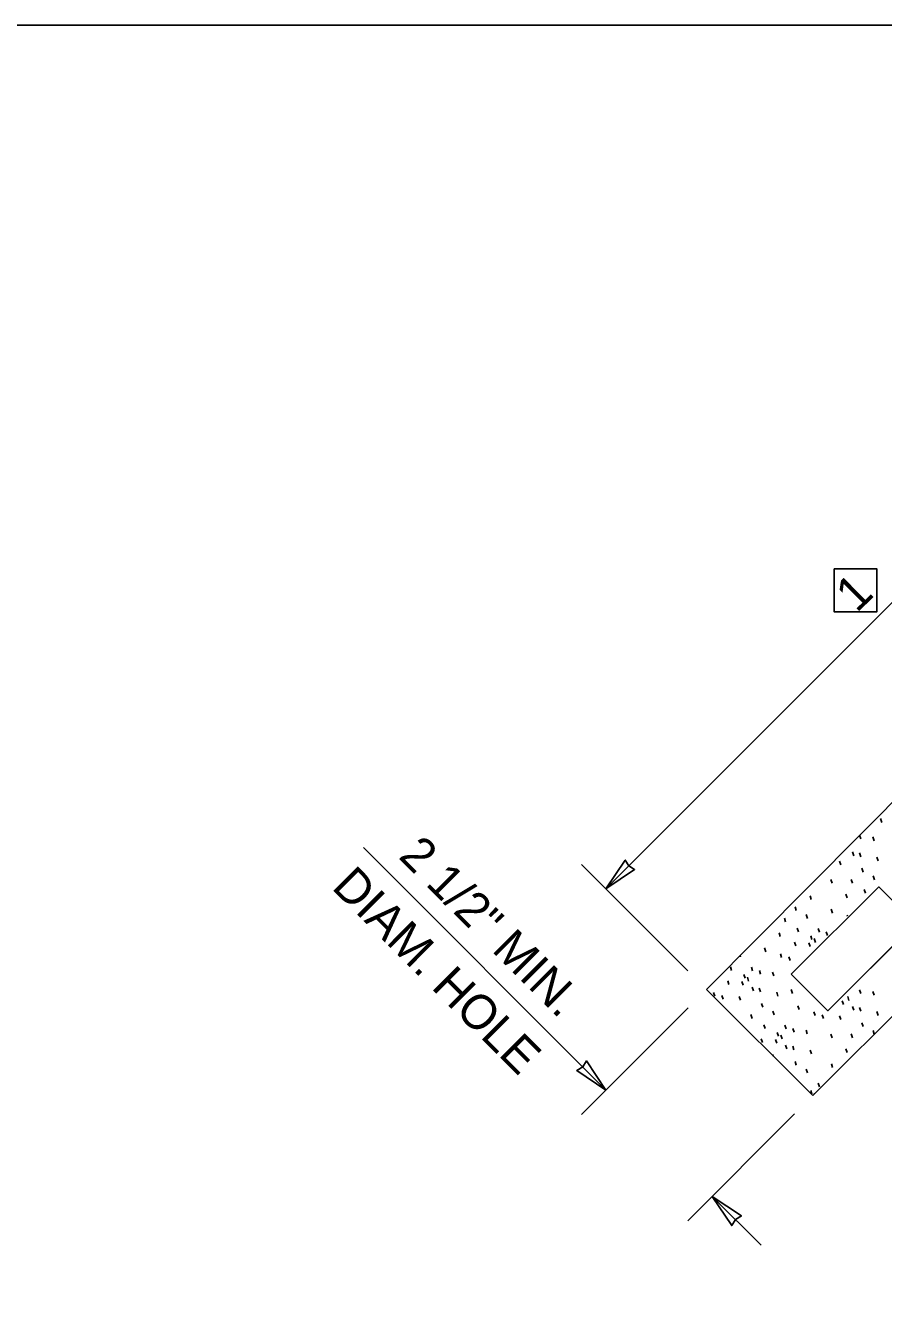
# Model space of a CAD drawing. Extents: x 99861 to 103151, y 100000 to 102076.
# Drawn here: x 101342 to 101740, y 101489 to 102076 of the extents above; entities that cross this region are included whole.
import ezdxf

# ---------------------------------------------------------------- set-up
doc = ezdxf.new("R2010")
doc.units = 0
for name, color, linetype in [('Level 1', 7, 'Continuous'), ('Level 15', 7, 'Continuous'), ('Level 2', 7, 'Continuous'), ('Level 20', 7, 'Continuous'), ('Level 6', 7, 'Continuous'), ('Level 8', 7, 'Continuous')]:
    doc.layers.add(name, color=color, linetype=linetype)

# ---------------------------------------------------------------- blocks, each defined once
blk = doc.blocks.new('T')
at = {"layer": 'Level 15'}
blk.add_lwpolyline([(0, 0), (-22.829, 2.985), (-21.773, 0), (-22.83, -2.985)], close=True, dxfattribs=at)

msp = doc.modelspace()

# ---------------------------------------------------------------- linework, layer by layer
at = {"layer": 'Level 1'}
msp.add_lwpolyline([(99861, 100000), (103150, 100000), (103150, 102076), (99861, 102076)], close=True, dxfattribs=at)
at = {"layer": 'Level 15'}
for p, q in [((101953.07, 102017.81), (101611.31, 101675.88)), ((101599.99, 101687.19), (101649.29, 101637.91))]:
    msp.add_line(p, q, dxfattribs=at)
msp.add_lwpolyline([(101611.31, 101675.88), (101620.24, 101689.18), (101621.91, 101686.49), (101624.6, 101684.82)], close=True, dxfattribs=at)
at = {"layer": 'Level 2'}
for p, q in [((101805.19, 101777.43), (101657.99, 101629.22)), ((101854.86, 101727.74), (101707.23, 101580.01)), ((101707.23, 101580.01), (101657.99, 101629.22))]:
    msp.add_line(p, q, dxfattribs=at)
at = {"layer": 'Level 20'}
for p, q in [((101498.85, 101694.95), (101611.33, 101582.54)), ((101649.5, 101620.73), (101600.02, 101571.22)), ((101698.75, 101571.52), (101649.27, 101522.01)), ((101660.58, 101533.33), (101683.21, 101510.71)), ((101671.89, 101522.02), (101660.58, 101533.33))]:
    msp.add_line(p, q, dxfattribs=at)
msp.add_lwpolyline([(101717.08, 101824.1), (101736.94, 101824.1), (101736.94, 101804.25), (101717.08, 101804.25)], close=True, dxfattribs=at)
at = {"layer": 'Level 6'}
for p, q in [((101697.21, 101636.33), (101737.79, 101676.72)), ((101737.79, 101676.72), (101754.72, 101659.71)), ((101754.72, 101659.71), (101714.14, 101619.32)), ((101714.14, 101619.32), (101697.21, 101636.33))]:
    msp.add_line(p, q, dxfattribs=at)
msp.add_lwpolyline([(101697.21, 101636.33), (101714.14, 101619.32), (101754.72, 101659.71), (101737.79, 101676.72), (101697.21, 101636.33)], dxfattribs=at)
at = {"layer": 'Level 8'}
for p, q in [((101739.23, 101706.65), (101738.66, 101708.4)), ((101729.48, 101698.95), (101728.93, 101700.65)), ((101735.62, 101698.16), (101735.05, 101699.91)), ((101726.18, 101691.17), (101725.61, 101692.92)), ((101729.46, 101690.74), (101728.89, 101692.49)), ((101720.14, 101686.9), (101719.56, 101688.65)), ((101737.53, 101688.82), (101736.96, 101690.57)), ((101730.54, 101683.63), (101729.97, 101685.37)), ((101735.75, 101680.06), (101735.18, 101681.8)), ((101716.14, 101678.41), (101715.57, 101680.16)), ((101725.6, 101678.45), (101725.02, 101680.2)), ((101731.58, 101673.78), (101731.01, 101675.53)), ((101706.53, 101670.93), (101705.96, 101672.67)), ((101723.15, 101671.62), (101722.58, 101673.37)), ((101699.54, 101665.73), (101698.97, 101667.48)), ((101704.75, 101662.16), (101704.18, 101663.91)), ((101716.37, 101664.61), (101715.8, 101666.36)), ((101723.34, 101663.11), (101723.17, 101663.65)), ((101694.6, 101660.56), (101694.03, 101662.3)), ((101700.59, 101655.89), (101700.01, 101657.63)), ((101710.3, 101655.69), (101709.73, 101657.44)), ((101692.16, 101653.73), (101691.59, 101655.48)), ((101706.8, 101652.32), (101706.23, 101654.07)), ((101708.48, 101651.02), (101707.91, 101652.76)), ((101713.97, 101654.26), (101713.42, 101655.94)), ((101685.37, 101646.72), (101684.8, 101648.46)), ((101692.74, 101644.01), (101692.17, 101645.75)), ((101699.33, 101649.36), (101698.76, 101651.1)), ((101705.95, 101649.1), (101705.38, 101650.85)), ((101669.59, 101637.99), (101669.02, 101639.74)), ((101673.76, 101644.27), (101673.55, 101644.89)), ((101696.66, 101642.58), (101696.09, 101644.32)), ((101675.81, 101634.42), (101675.24, 101636.17)), ((101677.48, 101633.12), (101676.91, 101634.87)), ((101679.31, 101637.8), (101678.73, 101639.54)), ((101683, 101636.3), (101682.43, 101638.05)), ((101689.13, 101635.52), (101688.56, 101637.26)), ((101668.33, 101631.46), (101667.76, 101633.21)), ((101674.96, 101631.2), (101674.39, 101632.95)), ((101679.7, 101628.52), (101679.13, 101630.27)), ((101682.97, 101628.09), (101682.4, 101629.84)), ((101697.8, 101627.4), (101697.23, 101629.15)), ((101729.5, 101627.34), (101728.93, 101629.09)), ((101735.63, 101626.56), (101735.06, 101628.3)), ((101661.75, 101626.11), (101661.18, 101627.86)), ((101665.67, 101624.68), (101665.1, 101626.43)), ((101673.65, 101624.26), (101673.08, 101626)), ((101684.05, 101620.98), (101683.48, 101622.73)), ((101691.04, 101626.18), (101690.47, 101627.92)), ((101721.46, 101622.24), (101720.89, 101623.99)), ((101723.99, 101624.16), (101723.41, 101625.91)), ((101679.11, 101615.8), (101678.54, 101617.55)), ((101689.26, 101617.41), (101688.69, 101619.16)), ((101700.88, 101619.86), (101700.31, 101621.61)), ((101708.25, 101617.15), (101707.68, 101618.9)), ((101712.17, 101615.72), (101711.6, 101617.47)), ((101720.15, 101615.3), (101719.58, 101617.04)), ((101726.2, 101619.56), (101725.63, 101621.31)), ((101729.47, 101619.13), (101728.9, 101620.88)), ((101737.54, 101617.21), (101736.97, 101618.96)), ((101685.1, 101611.14), (101684.52, 101612.88)), ((101694.81, 101610.94), (101694.24, 101612.69)), ((101698.5, 101609.45), (101697.93, 101611.19)), ((101704.64, 101608.66), (101704.07, 101610.41)), ((101730.56, 101612.02), (101729.98, 101613.77)), ((101683.84, 101604.61), (101683.27, 101606.35)), ((101690.47, 101604.35), (101689.89, 101606.09)), ((101691.31, 101607.57), (101690.74, 101609.31)), ((101692.99, 101606.26), (101692.42, 101608.01)), ((101716.16, 101606.8), (101715.59, 101608.55)), ((101725.61, 101606.84), (101725.04, 101608.59)), ((101735.74, 101608.53), (101735.19, 101610.2)), ((101688.83, 101598.4), (101688.58, 101599.15)), ((101695.2, 101601.67), (101694.63, 101603.41)), ((101698.48, 101601.24), (101697.91, 101602.98)), ((101706.55, 101599.32), (101705.98, 101601.07)), ((101723.17, 101600.02), (101722.6, 101601.76)), ((101731.05, 101603.85), (101731.03, 101603.92)), ((101699.56, 101594.12), (101698.99, 101595.87)), ((101716.39, 101593.01), (101715.81, 101594.75)), ((101704.77, 101590.55), (101704.2, 101592.3)), ((101706.82, 101580.71), (101706.25, 101582.46)), ((101708.04, 101580.82), (101707.92, 101581.15)), ((101710.32, 101584.08), (101709.75, 101585.83))]:
    msp.add_line(p, q, dxfattribs=at)

# ---------------------------------------------------------------- block references
at = {"layer": 'Level 20', "xscale": 0.7008322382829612}
for p, yscale, rotation in [((101611.33, 101582.54), -1.072026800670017, -44.98115163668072), ((101660.58, 101533.33), -1.0720268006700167, 135.01884836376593)]:
    msp.add_blockref('T', p, dxfattribs=dict(at, yscale=yscale, rotation=rotation))

# ---------------------------------------------------------------- texts
at = {"layer": 'Level 20'}
for s, rotation, p in [('1', 44.70313, (101727.6, 101803.45)), ('2 1/2" MIN.', 315.01885, (101514.68, 101690.43)), ('DIAM. HOLE ', 315.01885, (101483.7, 101676.16))]:
    msp.add_text(s, height=16, rotation=rotation, dxfattribs=at).set_placement(p)

doc.saveas('drawing.dxf')
